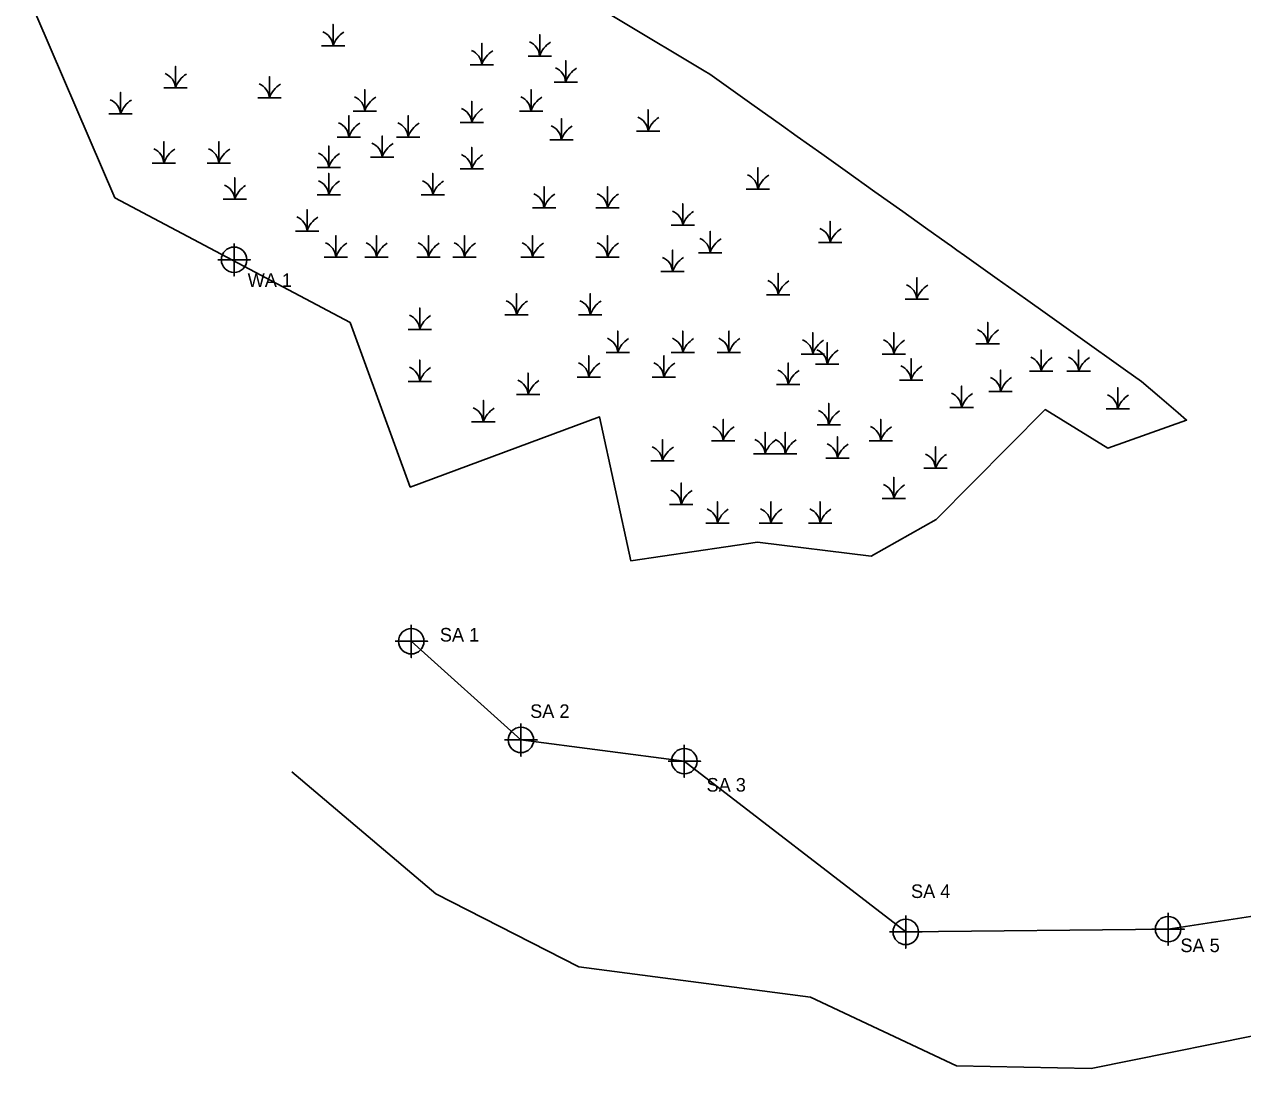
# Model space of a CAD drawing. Extents: x 2058476 to 2058911, y 688598 to 689103.
# Drawn here: x 2058475.6 to 2058700, y 688719.7 to 688912 of the extents above; entities that cross this region are included whole.
import ezdxf

# ---------------------------------------------------------------- set-up
doc = ezdxf.new("R2010")
doc.units = 0
for name, color, linetype in [('Exist Environmental Wetland Boundary', 7, 'Continuous'), ('Exist Environmental Wetland Boundary Cogo Comment', 7, 'Continuous'), ('Exist Environmental Wetland Boundary Cogo Point CELL', 7, 'Continuous'), ('Exist Hydro Jurisdictional Stream or Body of Water NEU Mitigable', 7, 'Continuous'), ('Exist Hydro Jurisdictional Stream or Body of Water NEU Mitigable Cogo Comment', 7, 'Continuous'), ('Exist Hydro Jurisdictional Stream or Body of Water NEU Mitigable Cogo Point CELL', 7, 'Continuous'), ('Exist Hydro Swamp or Marsh', 7, 'Continuous')]:
    doc.layers.add(name, color=color, linetype=linetype)

msp = doc.modelspace()

# ---------------------------------------------------------------- linework, layer by layer
at = {"layer": 'Exist Environmental Wetland Boundary'}
msp.add_lwpolyline([(2058475.61, 688918.78), (2058492.26, 688880.08), (2058535.62, 688857.12), (2058546.68, 688826.81), (2058581.55, 688839.73), (2058587.3, 688813.26), (2058610.64, 688816.7), (2058631.58, 688814.09), (2058643.57, 688820.85), (2058663.64, 688841.09), (2058675.15, 688833.97), (2058689.69, 688839.14), (2058688.13, 688840.48), (2058684.7, 688843.42), (2058681.4, 688846.24), (2058678.44, 688848.35), (2058669.64, 688854.61), (2058664.05, 688858.59), (2058659.98, 688861.48), (2058654.78, 688865.19), (2058648.75, 688869.48), (2058647.37, 688870.46), (2058646.36, 688871.17), (2058645.55, 688871.75), (2058641.62, 688874.54), (2058637.4, 688877.55), (2058632.28, 688881.2), (2058626.8, 688885.09), (2058622.49, 688888.16), (2058617.97, 688891.37), (2058615.08, 688893.43), (2058609.59, 688897.34), (2058601.84, 688902.85), (2058600.82, 688903.46), (2058598.04, 688905.12), (2058588.45, 688910.87), (2058580.43, 688915.67)], dxfattribs=at)
at = {"layer": 'Exist Environmental Wetland Boundary Cogo Point CELL'}
msp.add_lwpolyline([(2058514.24, 688871.67), (2058514.24, 688865.67), (2058514.24, 688868.67), (2058517.24, 688868.67), (2058511.24, 688868.67)], dxfattribs=at)
msp.add_lwpolyline([(2058514.24, 688871.67), (2058514.24, 688865.67), (2058514.24, 688868.67), (2058517.24, 688868.67), (2058511.24, 688868.67)], dxfattribs=at)
msp.add_circle((2058514.24, 688868.67), 2.34, dxfattribs=at)
msp.add_circle((2058514.24, 688868.67), 2.34, dxfattribs=at)
at = {"layer": 'Exist Hydro Jurisdictional Stream or Body of Water NEU Mitigable'}
for points in [[(2058546.88, 688798.43), (2058567.07, 688780.26), (2058597.17, 688776.35), (2058637.95, 688744.91), (2058686.27, 688745.42), (2058733.39, 688752.64), (2058799.32, 688761.71)], [(2058818.52, 688747.47), (2058803.98, 688740.74), (2058756.88, 688736.43), (2058742.34, 688734.01), (2058709.24, 688727.28), (2058672.09, 688719.74), (2058647.32, 688720.28), (2058620.41, 688732.93), (2058577.76, 688738.46), (2058551.38, 688751.92), (2058524.85, 688774.39)]]:
    msp.add_lwpolyline(points, dxfattribs=at)
at = {"layer": 'Exist Hydro Jurisdictional Stream or Body of Water NEU Mitigable Cogo Point CELL'}
for points in [[(2058546.88, 688801.43), (2058546.88, 688795.43), (2058546.88, 688798.43), (2058549.88, 688798.43), (2058543.88, 688798.43)], [(2058567.07, 688783.26), (2058567.07, 688777.26), (2058567.07, 688780.26), (2058570.07, 688780.26), (2058564.07, 688780.26)], [(2058597.17, 688779.35), (2058597.17, 688773.35), (2058597.17, 688776.35), (2058600.17, 688776.35), (2058594.17, 688776.35)], [(2058637.95, 688747.91), (2058637.95, 688741.91), (2058637.95, 688744.91), (2058640.95, 688744.91), (2058634.95, 688744.91)], [(2058686.27, 688748.42), (2058686.27, 688742.42), (2058686.27, 688745.42), (2058689.27, 688745.42), (2058683.27, 688745.42)]]:
    msp.add_lwpolyline(points, dxfattribs=at)
for centre in [(2058546.88, 688798.43), (2058567.07, 688780.26), (2058597.17, 688776.35), (2058637.95, 688744.91), (2058686.27, 688745.42)]:
    msp.add_circle(centre, 2.34, dxfattribs=at)
at = {"layer": 'Exist Hydro Swamp or Marsh'}
for points in [[(2058530.32, 688908.04), (2058532.47, 688908.04), (2058532.47, 688911.99), (2058532.47, 688908.04), (2058534.62, 688908.04)], [(2058557.73, 688904.58), (2058559.88, 688904.58), (2058559.88, 688908.53), (2058559.88, 688904.58), (2058562.03, 688904.58)], [(2058568.38, 688906.18), (2058570.53, 688906.18), (2058570.53, 688910.12), (2058570.53, 688906.18), (2058572.68, 688906.18)], [(2058501.3, 688900.32), (2058503.46, 688900.32), (2058503.46, 688904.27), (2058503.46, 688900.32), (2058505.61, 688900.32)], [(2058573.17, 688901.39), (2058575.32, 688901.39), (2058575.32, 688905.33), (2058575.32, 688901.39), (2058577.47, 688901.39)], [(2058518.61, 688898.46), (2058520.76, 688898.46), (2058520.76, 688902.4), (2058520.76, 688898.46), (2058522.91, 688898.46)], [(2058491.19, 688895.53), (2058493.34, 688895.53), (2058493.34, 688899.47), (2058493.34, 688895.53), (2058495.49, 688895.53)], [(2058536.17, 688896.06), (2058538.32, 688896.06), (2058538.32, 688900), (2058538.32, 688896.06), (2058540.47, 688896.06)], [(2058566.78, 688896.06), (2058568.93, 688896.06), (2058568.93, 688900), (2058568.93, 688896.06), (2058571.08, 688896.06)], [(2058555.87, 688893.93), (2058558.02, 688893.93), (2058558.02, 688897.87), (2058558.02, 688893.93), (2058560.17, 688893.93)], [(2058533.24, 688891.27), (2058535.39, 688891.27), (2058535.39, 688895.21), (2058535.39, 688891.27), (2058537.54, 688891.27)], [(2058544.16, 688891.27), (2058546.31, 688891.27), (2058546.31, 688895.21), (2058546.31, 688891.27), (2058548.46, 688891.27)], [(2058572.37, 688890.73), (2058574.52, 688890.73), (2058574.52, 688894.68), (2058574.52, 688890.73), (2058576.67, 688890.73)], [(2058588.34, 688892.33), (2058590.49, 688892.33), (2058590.49, 688896.28), (2058590.49, 688892.33), (2058592.64, 688892.33)], [(2058499.18, 688886.47), (2058501.33, 688886.47), (2058501.33, 688890.42), (2058501.33, 688886.47), (2058503.48, 688886.47)], [(2058509.29, 688886.47), (2058511.44, 688886.47), (2058511.44, 688890.42), (2058511.44, 688886.47), (2058513.59, 688886.47)], [(2058539.37, 688887.54), (2058541.52, 688887.54), (2058541.52, 688891.48), (2058541.52, 688887.54), (2058543.67, 688887.54)], [(2058529.52, 688885.67), (2058531.67, 688885.67), (2058531.67, 688889.62), (2058531.67, 688885.67), (2058533.82, 688885.67)], [(2058555.87, 688885.41), (2058558.02, 688885.41), (2058558.02, 688889.35), (2058558.02, 688885.41), (2058560.17, 688885.41)], [(2058608.57, 688881.68), (2058610.72, 688881.68), (2058610.72, 688885.63), (2058610.72, 688881.68), (2058612.87, 688881.68)], [(2058512.22, 688879.82), (2058514.37, 688879.82), (2058514.37, 688883.76), (2058514.37, 688879.82), (2058516.52, 688879.82)], [(2058529.52, 688880.62), (2058531.67, 688880.62), (2058531.67, 688884.56), (2058531.67, 688880.62), (2058533.82, 688880.62)], [(2058548.68, 688880.62), (2058550.83, 688880.62), (2058550.83, 688884.56), (2058550.83, 688880.62), (2058552.98, 688880.62)], [(2058569.18, 688878.22), (2058571.33, 688878.22), (2058571.33, 688882.16), (2058571.33, 688878.22), (2058573.48, 688878.22)], [(2058580.89, 688878.22), (2058583.04, 688878.22), (2058583.04, 688882.16), (2058583.04, 688878.22), (2058585.19, 688878.22)], [(2058594.73, 688875.02), (2058596.88, 688875.02), (2058596.88, 688878.97), (2058596.88, 688875.02), (2058599.03, 688875.02)], [(2058525.53, 688873.96), (2058527.68, 688873.96), (2058527.68, 688877.9), (2058527.68, 688873.96), (2058529.83, 688873.96)], [(2058621.88, 688871.83), (2058624.03, 688871.83), (2058624.03, 688875.77), (2058624.03, 688871.83), (2058626.18, 688871.83)], [(2058530.85, 688869.17), (2058533, 688869.17), (2058533, 688873.11), (2058533, 688869.17), (2058535.15, 688869.17)], [(2058538.3, 688869.17), (2058540.45, 688869.17), (2058540.45, 688873.11), (2058540.45, 688869.17), (2058542.6, 688869.17)], [(2058547.88, 688869.17), (2058550.03, 688869.17), (2058550.03, 688873.11), (2058550.03, 688869.17), (2058552.18, 688869.17)], [(2058554.54, 688869.17), (2058556.69, 688869.17), (2058556.69, 688873.11), (2058556.69, 688869.17), (2058558.84, 688869.17)], [(2058567.05, 688869.17), (2058569.2, 688869.17), (2058569.2, 688873.11), (2058569.2, 688869.17), (2058571.35, 688869.17)], [(2058580.89, 688869.17), (2058583.04, 688869.17), (2058583.04, 688873.11), (2058583.04, 688869.17), (2058585.19, 688869.17)], [(2058599.78, 688869.96), (2058601.93, 688869.96), (2058601.93, 688873.91), (2058601.93, 688869.96), (2058604.08, 688869.96)], [(2058592.86, 688866.5), (2058595.01, 688866.5), (2058595.01, 688870.45), (2058595.01, 688866.5), (2058597.16, 688866.5)], [(2058612.29, 688862.24), (2058614.44, 688862.24), (2058614.44, 688866.19), (2058614.44, 688862.24), (2058616.59, 688862.24)], [(2058612.29, 688862.24), (2058614.44, 688862.24), (2058614.44, 688866.19), (2058614.44, 688862.24), (2058616.59, 688862.24)], [(2058637.84, 688861.44), (2058640, 688861.44), (2058640, 688865.39), (2058640, 688861.44), (2058642.15, 688861.44)], [(2058564.12, 688858.51), (2058566.27, 688858.51), (2058566.27, 688862.46), (2058566.27, 688858.51), (2058568.42, 688858.51)], [(2058577.69, 688858.51), (2058579.84, 688858.51), (2058579.84, 688862.46), (2058579.84, 688858.51), (2058581.99, 688858.51)], [(2058546.29, 688855.85), (2058548.44, 688855.85), (2058548.44, 688859.8), (2058548.44, 688855.85), (2058550.59, 688855.85)], [(2058650.89, 688853.19), (2058653.04, 688853.19), (2058653.04, 688857.13), (2058653.04, 688853.19), (2058655.19, 688853.19)], [(2058582.75, 688851.59), (2058584.9, 688851.59), (2058584.9, 688855.54), (2058584.9, 688851.59), (2058587.05, 688851.59)], [(2058594.73, 688851.59), (2058596.88, 688851.59), (2058596.88, 688855.54), (2058596.88, 688851.59), (2058599.03, 688851.59)], [(2058603.24, 688851.59), (2058605.39, 688851.59), (2058605.39, 688855.54), (2058605.39, 688851.59), (2058607.54, 688851.59)], [(2058603.24, 688851.59), (2058605.39, 688851.59), (2058605.39, 688855.54), (2058605.39, 688851.59), (2058607.54, 688851.59)], [(2058618.68, 688851.32), (2058620.83, 688851.32), (2058620.83, 688855.27), (2058620.83, 688851.32), (2058622.98, 688851.32)], [(2058633.59, 688851.32), (2058635.74, 688851.32), (2058635.74, 688855.27), (2058635.74, 688851.32), (2058637.89, 688851.32)], [(2058621.34, 688849.46), (2058623.49, 688849.46), (2058623.49, 688853.41), (2058623.49, 688849.46), (2058625.64, 688849.46)], [(2058660.73, 688848.13), (2058662.88, 688848.13), (2058662.88, 688852.07), (2058662.88, 688848.13), (2058665.04, 688848.13)], [(2058667.65, 688848.13), (2058669.8, 688848.13), (2058669.8, 688852.07), (2058669.8, 688848.13), (2058671.96, 688848.13)], [(2058546.29, 688846.27), (2058548.44, 688846.27), (2058548.44, 688850.21), (2058548.44, 688846.27), (2058550.59, 688846.27)], [(2058546.29, 688846.27), (2058548.44, 688846.27), (2058548.44, 688850.21), (2058548.44, 688846.27), (2058550.59, 688846.27)], [(2058577.43, 688847.06), (2058579.58, 688847.06), (2058579.58, 688851.01), (2058579.58, 688847.06), (2058581.73, 688847.06)], [(2058591.27, 688847.06), (2058593.42, 688847.06), (2058593.42, 688851.01), (2058593.42, 688847.06), (2058595.57, 688847.06)], [(2058591.27, 688847.06), (2058593.42, 688847.06), (2058593.42, 688851.01), (2058593.42, 688847.06), (2058595.57, 688847.06)], [(2058614.16, 688845.73), (2058616.31, 688845.73), (2058616.31, 688849.68), (2058616.31, 688845.73), (2058618.46, 688845.73)], [(2058636.78, 688846.53), (2058638.93, 688846.53), (2058638.93, 688850.48), (2058638.93, 688846.53), (2058641.08, 688846.53)], [(2058566.25, 688843.87), (2058568.4, 688843.87), (2058568.4, 688847.81), (2058568.4, 688843.87), (2058570.55, 688843.87)], [(2058653.28, 688844.4), (2058655.43, 688844.4), (2058655.43, 688848.35), (2058655.43, 688844.4), (2058657.58, 688844.4)], [(2058646.1, 688841.47), (2058648.25, 688841.47), (2058648.25, 688845.42), (2058648.25, 688841.47), (2058650.4, 688841.47)], [(2058674.84, 688841.21), (2058676.99, 688841.21), (2058676.99, 688845.15), (2058676.99, 688841.21), (2058679.14, 688841.21)], [(2058558, 688838.81), (2058560.15, 688838.81), (2058560.15, 688842.76), (2058560.15, 688838.81), (2058562.3, 688838.81)], [(2058558, 688838.81), (2058560.15, 688838.81), (2058560.15, 688842.76), (2058560.15, 688838.81), (2058562.3, 688838.81)], [(2058621.61, 688838.28), (2058623.76, 688838.28), (2058623.76, 688842.22), (2058623.76, 688838.28), (2058625.91, 688838.28)], [(2058602.18, 688835.35), (2058604.33, 688835.35), (2058604.33, 688839.29), (2058604.33, 688835.35), (2058606.48, 688835.35)], [(2058631.19, 688835.35), (2058633.34, 688835.35), (2058633.34, 688839.29), (2058633.34, 688835.35), (2058635.49, 688835.35)], [(2058609.9, 688832.95), (2058612.05, 688832.95), (2058612.05, 688836.9), (2058612.05, 688832.95), (2058614.2, 688832.95)], [(2058613.62, 688832.95), (2058615.77, 688832.95), (2058615.77, 688836.9), (2058615.77, 688832.95), (2058617.92, 688832.95)], [(2058591, 688831.62), (2058593.15, 688831.62), (2058593.15, 688835.57), (2058593.15, 688831.62), (2058595.3, 688831.62)], [(2058623.21, 688832.15), (2058625.36, 688832.15), (2058625.36, 688836.1), (2058625.36, 688832.15), (2058627.51, 688832.15)], [(2058641.3, 688830.29), (2058643.46, 688830.29), (2058643.46, 688834.23), (2058643.46, 688830.29), (2058645.61, 688830.29)], [(2058594.46, 688823.63), (2058596.61, 688823.63), (2058596.61, 688827.58), (2058596.61, 688823.63), (2058598.76, 688823.63)], [(2058633.59, 688824.7), (2058635.74, 688824.7), (2058635.74, 688828.64), (2058635.74, 688824.7), (2058637.89, 688824.7)], [(2058601.11, 688820.17), (2058603.27, 688820.17), (2058603.27, 688824.12), (2058603.27, 688820.17), (2058605.42, 688820.17)], [(2058610.96, 688820.17), (2058613.11, 688820.17), (2058613.11, 688824.12), (2058613.11, 688820.17), (2058615.26, 688820.17)], [(2058620.01, 688820.17), (2058622.16, 688820.17), (2058622.16, 688824.12), (2058622.16, 688820.17), (2058624.31, 688820.17)]]:
    msp.add_lwpolyline(points, dxfattribs=at)
for centre, radius, start, end in [((2058529.4, 688907.82), 3.07, 4.1403, 67.535), ((2058537.03, 688906.53), 4.81, 122.1274, 161.6222), ((2058567.46, 688905.96), 3.07, 4.1403, 67.535), ((2058575.09, 688904.66), 4.81, 122.1274, 161.6222), ((2058556.81, 688904.36), 3.07, 4.1403, 67.535), ((2058564.44, 688903.07), 4.81, 122.1274, 161.6222), ((2058572.25, 688901.16), 3.07, 4.1403, 67.535), ((2058579.88, 688899.87), 4.81, 122.1274, 161.6222), ((2058500.39, 688900.1), 3.07, 4.1403, 67.535), ((2058508.02, 688898.8), 4.81, 122.1274, 161.6222), ((2058517.69, 688898.23), 3.07, 4.1403, 67.535), ((2058525.32, 688896.94), 4.81, 122.1274, 161.6222), ((2058490.27, 688895.3), 3.07, 4.1403, 67.535), ((2058497.9, 688894.01), 4.81, 122.1274, 161.6222), ((2058535.26, 688895.84), 3.07, 4.1403, 67.535), ((2058542.88, 688894.54), 4.81, 122.1274, 161.6222), ((2058565.86, 688895.84), 3.07, 4.1403, 67.535), ((2058573.49, 688894.54), 4.81, 122.1274, 161.6222), ((2058554.95, 688893.71), 3.07, 4.1403, 67.535), ((2058562.58, 688892.41), 4.81, 122.1274, 161.6222), ((2058587.42, 688892.11), 3.07, 4.1403, 67.535), ((2058595.05, 688890.82), 4.81, 122.1274, 161.6222), ((2058532.33, 688891.04), 3.07, 4.1403, 67.535), ((2058539.95, 688889.75), 4.81, 122.1274, 161.6222), ((2058543.24, 688891.04), 3.07, 4.1403, 67.535), ((2058550.87, 688889.75), 4.81, 122.1274, 161.6222), ((2058571.45, 688890.51), 3.07, 4.1403, 67.535), ((2058579.08, 688889.22), 4.81, 122.1274, 161.6222), ((2058538.45, 688887.32), 3.07, 4.1403, 67.535), ((2058546.08, 688886.02), 4.81, 122.1274, 161.6222), ((2058498.26, 688886.25), 3.07, 4.1403, 67.535), ((2058505.89, 688884.96), 4.81, 122.1274, 161.6222), ((2058508.37, 688886.25), 3.07, 4.1403, 67.535), ((2058516, 688884.96), 4.81, 122.1274, 161.6222), ((2058528.6, 688885.45), 3.07, 4.1403, 67.535), ((2058536.23, 688884.16), 4.81, 122.1274, 161.6222), ((2058554.95, 688885.19), 3.07, 4.1403, 67.535), ((2058562.58, 688883.89), 4.81, 122.1274, 161.6222), ((2058607.65, 688881.46), 3.07, 4.1403, 67.535), ((2058615.28, 688880.17), 4.81, 122.1274, 161.6222), ((2058511.3, 688879.59), 3.07, 4.1403, 67.535), ((2058518.93, 688878.3), 4.81, 122.1274, 161.6222), ((2058528.6, 688880.39), 3.07, 4.1403, 67.535), ((2058536.23, 688879.1), 4.81, 122.1274, 161.6222), ((2058547.76, 688880.39), 3.07, 4.1403, 67.535), ((2058555.39, 688879.1), 4.81, 122.1274, 161.6222), ((2058568.26, 688878), 3.07, 4.1403, 67.535), ((2058575.89, 688876.7), 4.81, 122.1274, 161.6222), ((2058579.97, 688878), 3.07, 4.1403, 67.535), ((2058587.6, 688876.7), 4.81, 122.1274, 161.6222), ((2058593.81, 688874.8), 3.07, 4.1403, 67.535), ((2058601.44, 688873.51), 4.81, 122.1274, 161.6222), ((2058524.61, 688873.74), 3.07, 4.1403, 67.535), ((2058532.24, 688872.44), 4.81, 122.1274, 161.6222), ((2058620.96, 688871.61), 3.07, 4.1403, 67.535), ((2058628.59, 688870.31), 4.81, 122.1274, 161.6222), ((2058598.87, 688869.74), 3.07, 4.1403, 67.535), ((2058606.49, 688868.45), 4.81, 122.1274, 161.6222), ((2058529.93, 688868.94), 3.07, 4.1403, 67.535), ((2058537.56, 688867.65), 4.81, 122.1274, 161.6222), ((2058537.38, 688868.94), 3.07, 4.1403, 67.535), ((2058545.01, 688867.65), 4.81, 122.1274, 161.6222), ((2058546.97, 688868.94), 3.07, 4.1403, 67.535), ((2058554.59, 688867.65), 4.81, 122.1274, 161.6222), ((2058553.62, 688868.94), 3.07, 4.1403, 67.535), ((2058561.25, 688867.65), 4.81, 122.1274, 161.6222), ((2058566.13, 688868.94), 3.07, 4.1403, 67.535), ((2058573.76, 688867.65), 4.81, 122.1274, 161.6222), ((2058579.97, 688868.94), 3.07, 4.1403, 67.535), ((2058587.6, 688867.65), 4.81, 122.1274, 161.6222), ((2058591.95, 688866.28), 3.07, 4.1403, 67.535), ((2058599.57, 688864.99), 4.81, 122.1274, 161.6222), ((2058611.38, 688862.02), 3.07, 4.1403, 67.535), ((2058611.38, 688862.02), 3.07, 4.1403, 67.535), ((2058619, 688860.73), 4.81, 122.1274, 161.6222), ((2058619, 688860.73), 4.81, 122.1274, 161.6222), ((2058636.93, 688861.22), 3.07, 4.1403, 67.535), ((2058644.56, 688859.93), 4.81, 122.1274, 161.6222), ((2058563.2, 688858.29), 3.07, 4.1403, 67.535), ((2058570.83, 688857), 4.81, 122.1274, 161.6222), ((2058576.78, 688858.29), 3.07, 4.1403, 67.535), ((2058584.4, 688857), 4.81, 122.1274, 161.6222), ((2058545.37, 688855.63), 3.07, 4.1403, 67.535), ((2058553, 688854.34), 4.81, 122.1274, 161.6222), ((2058581.83, 688851.37), 3.07, 4.1403, 67.535), ((2058593.81, 688851.37), 3.07, 4.1403, 67.535), ((2058602.33, 688851.37), 3.07, 4.1403, 67.535), ((2058602.33, 688851.37), 3.07, 4.1403, 67.535), ((2058649.97, 688852.97), 3.07, 4.1403, 67.535), ((2058657.6, 688851.67), 4.81, 122.1274, 161.6222), ((2058589.46, 688850.08), 4.81, 122.1274, 161.6222), ((2058601.44, 688850.08), 4.81, 122.1274, 161.6222), ((2058609.95, 688850.08), 4.81, 122.1274, 161.6222), ((2058609.95, 688850.08), 4.81, 122.1274, 161.6222), ((2058617.77, 688851.1), 3.07, 4.1403, 67.535), ((2058625.39, 688849.81), 4.81, 122.1274, 161.6222), ((2058620.43, 688849.24), 3.07, 4.1403, 67.535), ((2058628.05, 688847.95), 4.81, 122.1274, 161.6222), ((2058632.67, 688851.1), 3.07, 4.1403, 67.535), ((2058640.3, 688849.81), 4.81, 122.1274, 161.6222), ((2058576.51, 688846.84), 3.07, 4.1403, 67.535), ((2058590.35, 688846.84), 3.07, 4.1403, 67.535), ((2058590.35, 688846.84), 3.07, 4.1403, 67.535), ((2058659.82, 688847.91), 3.07, 4.1403, 67.535), ((2058667.45, 688846.61), 4.81, 122.1274, 161.6222), ((2058666.74, 688847.91), 3.07, 4.1403, 67.535), ((2058674.37, 688846.61), 4.81, 122.1274, 161.6222), ((2058545.37, 688846.04), 3.07, 4.1403, 67.535), ((2058545.37, 688846.04), 3.07, 4.1403, 67.535), ((2058553, 688844.75), 4.81, 122.1274, 161.6222), ((2058553, 688844.75), 4.81, 122.1274, 161.6222), ((2058584.14, 688845.55), 4.81, 122.1274, 161.6222), ((2058597.98, 688845.55), 4.81, 122.1274, 161.6222), ((2058597.98, 688845.55), 4.81, 122.1274, 161.6222), ((2058613.24, 688845.51), 3.07, 4.1403, 67.535), ((2058620.87, 688844.22), 4.81, 122.1274, 161.6222), ((2058635.86, 688846.31), 3.07, 4.1403, 67.535), ((2058643.49, 688845.02), 4.81, 122.1274, 161.6222), ((2058565.33, 688843.65), 3.07, 4.1403, 67.535), ((2058572.96, 688842.35), 4.81, 122.1274, 161.6222), ((2058652.37, 688844.18), 3.07, 4.1403, 67.535), ((2058659.99, 688842.89), 4.81, 122.1274, 161.6222), ((2058645.18, 688841.25), 3.07, 4.1403, 67.535), ((2058652.81, 688839.96), 4.81, 122.1274, 161.6222), ((2058673.92, 688840.98), 3.07, 4.1403, 67.535), ((2058681.55, 688839.69), 4.81, 122.1274, 161.6222), ((2058557.08, 688838.59), 3.07, 4.1403, 67.535), ((2058557.08, 688838.59), 3.07, 4.1403, 67.535), ((2058564.71, 688837.29), 4.81, 122.1274, 161.6222), ((2058564.71, 688837.29), 4.81, 122.1274, 161.6222), ((2058620.69, 688838.06), 3.07, 4.1403, 67.535), ((2058628.32, 688836.76), 4.81, 122.1274, 161.6222), ((2058601.26, 688835.13), 3.07, 4.1403, 67.535), ((2058608.89, 688833.83), 4.81, 122.1274, 161.6222), ((2058630.27, 688835.13), 3.07, 4.1403, 67.535), ((2058637.9, 688833.83), 4.81, 122.1274, 161.6222), ((2058590.08, 688831.4), 3.07, 4.1403, 67.535), ((2058597.71, 688830.11), 4.81, 122.1274, 161.6222), ((2058608.98, 688832.73), 3.07, 4.1403, 67.535), ((2058616.61, 688831.44), 4.81, 122.1274, 161.6222), ((2058612.71, 688832.73), 3.07, 4.1403, 67.535), ((2058620.34, 688831.44), 4.81, 122.1274, 161.6222), ((2058622.29, 688831.93), 3.07, 4.1403, 67.535), ((2058629.92, 688830.64), 4.81, 122.1274, 161.6222), ((2058640.39, 688830.07), 3.07, 4.1403, 67.535), ((2058648.02, 688828.77), 4.81, 122.1274, 161.6222), ((2058632.67, 688824.48), 3.07, 4.1403, 67.535), ((2058640.3, 688823.18), 4.81, 122.1274, 161.6222), ((2058593.54, 688823.41), 3.07, 4.1403, 67.535), ((2058601.17, 688822.12), 4.81, 122.1274, 161.6222), ((2058600.2, 688819.95), 3.07, 4.1403, 67.535), ((2058610.05, 688819.95), 3.07, 4.1403, 67.535), ((2058619.1, 688819.95), 3.07, 4.1403, 67.535), ((2058607.83, 688818.66), 4.81, 122.1274, 161.6222), ((2058617.67, 688818.66), 4.81, 122.1274, 161.6222), ((2058626.72, 688818.66), 4.81, 122.1274, 161.6222)]:
    msp.add_arc(centre, radius, start, end, dxfattribs=at)

# ---------------------------------------------------------------- texts
at = {"layer": 'Exist Environmental Wetland Boundary Cogo Comment'}
msp.add_text('WA 1', height=2.5, dxfattribs=at).set_placement((2058516.74, 688863.67))
msp.add_text('WA 1', height=2.5, dxfattribs=at).set_placement((2058516.74, 688863.67))
at = {"layer": 'Exist Hydro Jurisdictional Stream or Body of Water NEU Mitigable Cogo Comment'}
for s, p in [('SA 1', (2058552.14, 688798.38)), ('SA 2', (2058568.77, 688784.31)), ('SA 3', (2058601.26, 688770.75)), ('SA 4', (2058638.92, 688751.16)), ('SA 5', (2058688.54, 688741.19))]:
    msp.add_text(s, height=2.5, dxfattribs=at).set_placement(p)

doc.saveas('drawing.dxf')
